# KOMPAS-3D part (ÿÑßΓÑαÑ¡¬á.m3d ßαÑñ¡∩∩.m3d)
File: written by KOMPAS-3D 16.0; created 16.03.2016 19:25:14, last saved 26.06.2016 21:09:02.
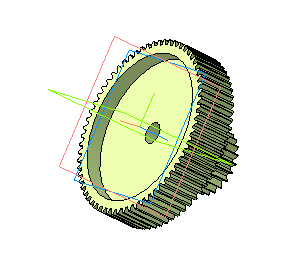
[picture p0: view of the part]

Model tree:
1. Эскиз:1
2. Операция выдавливания:1
     Расстояние 1 = 15
3. Эскиз:2
4. Операция выдавливания:2
     Расстояние 1 = 21
5. Эскиз:3
6. Вырезать элемент выдавливания:1
     Расстояние 1 = 100.5
7. Эскиз:4
8. Вырезать элемент выдавливания:2
     Расстояние 1 = 20.5
9. Массив по концентрической сетке:1  (with: Вырезать элемент выдавливания:2, Эскиз:4)  (65 pattern instances)
     Геометрический массив = 64; Шаг 2 = 360
10. Эскиз:5
11. Вырезать элемент выдавливания:3
     Расстояние 1 = 6
12. Эскиз:6
13. Эскиз:8
14. Вырезать элемент выдавливания:6
     Расстояние 1 = 6
15. Вырезать элемент выдавливания:9
     Расстояние 1 = 25
16. Массив по концентрической сетке:5  (with: Вырезать элемент выдавливания:9, Эскиз:6)  (22 pattern instances)
     Геометрический массив = 21; Шаг 2 = 360

Referenced files in C:\Users\Аня\Documents\: цпеупукп.jpg
Referenced files in E:\мои доки\: цвйЦЙ.png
